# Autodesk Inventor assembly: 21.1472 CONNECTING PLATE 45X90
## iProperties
Created: 2007-01
Part Number: 21.1472 CONNECTING PLATE 45X90
Document SubType Name: Assembly
Designer: Andy Moles
Mass: 187.953 g
Surface Area: 162.92 cm^2
Volume: 61.3682 cm^3
Density: 3.0627 g/cm^3
Author: Andy Moles
